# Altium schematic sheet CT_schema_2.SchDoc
size 313 x 200 mm
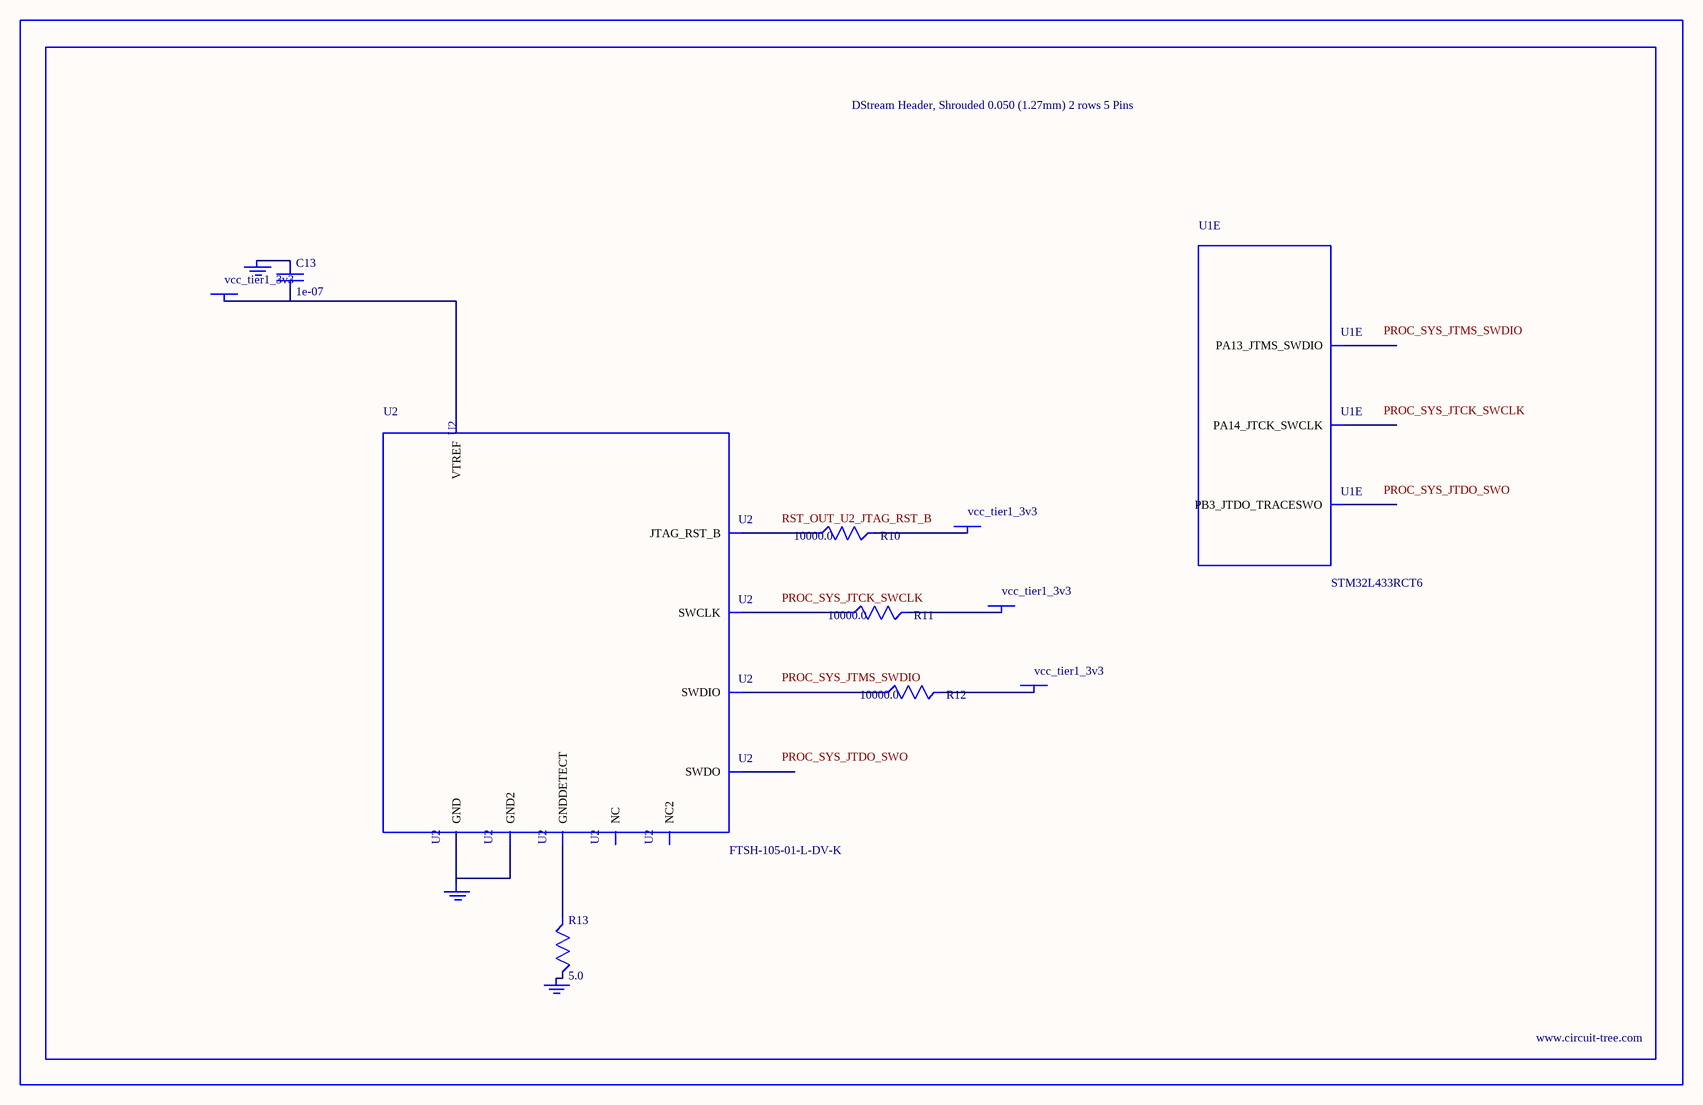
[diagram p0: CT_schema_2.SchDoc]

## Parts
BORDER1  (no value)
C13  1e-07  [C0402]
GND_INSTANCE_1_0  (no value)
GND_INSTANCE_1_1  (no value)
GND_INSTANCE_1_2  (no value)
POWER_INSTANCE_1_0  vcc_tier1_3v3
POWER_INSTANCE_1_1  vcc_tier1_3v3
POWER_INSTANCE_1_2  vcc_tier1_3v3
POWER_INSTANCE_1_3  vcc_tier1_3v3
R10  10000.0  [R0603]
R11  10000.0  [R0603]
R12  10000.0  [R0603]
R13  5.0  [R0603]
U1  STM32L433RCT6  [LQFP64]  (part E of 8)
U2  FTSH-105-01-L-DV-K  [SAMTEC_FTSH-105-01-L-DV-K]

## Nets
NetC13_1: C13.1 GND_INSTANCE_1_0.0(GND)
NetC13_2: C13.2 POWER_INSTANCE_1_0.0(PWR) U2.1(VTREF)
NetGND_INSTANCE_1_1_0: GND_INSTANCE_1_1.0(GND) R13.2
NetGND_INSTANCE_1_2_0: GND_INSTANCE_1_2.0(GND) U2.3(GND) U2.5(GND2)
NetPOWER_INSTANCE_1_1_0: POWER_INSTANCE_1_1.0(PWR) R12.2
NetPOWER_INSTANCE_1_2_0: POWER_INSTANCE_1_2.0(PWR) R11.2
NetPOWER_INSTANCE_1_3_0: POWER_INSTANCE_1_3.0(PWR) R10.2
NetR10_1: R10.1 U2.10(JTAG_RST_B)
NetR11_1: R11.1 U2.4(SWCLK)
NetR12_1: R12.1 U2.2(SWDIO)
NetR13_1: R13.1 U2.9(GNDDETECT)

Not connected (* = marked no-connect by the designer): U1 46(PA13_JTMS_SWDIO) 49(PA14_JTCK_SWCLK) 55(PB3_JTDO_TRACESWO); U2 6(SWDO) 7(NC) 8(NC2)

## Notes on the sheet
- Labels drawn without touching a wire or pin: PROC_SYS_JTCK_SWCLK, PROC_SYS_JTDO_SWO, PROC_SYS_JTMS_SWDIO, RST_OUT_U2_JTAG_RST_B

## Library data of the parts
BORDER1 = BORDER_PAGE1
C13 = C0402C104K3RACTU
GND_INSTANCE_1_0-GND_INSTANCE_1_2 = GND
POWER_INSTANCE_1_0-POWER_INSTANCE_1_3 = PWR
R10-R12 = RC0603JR-0710KL
R13 = ERJ-3GEYJ5R1V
